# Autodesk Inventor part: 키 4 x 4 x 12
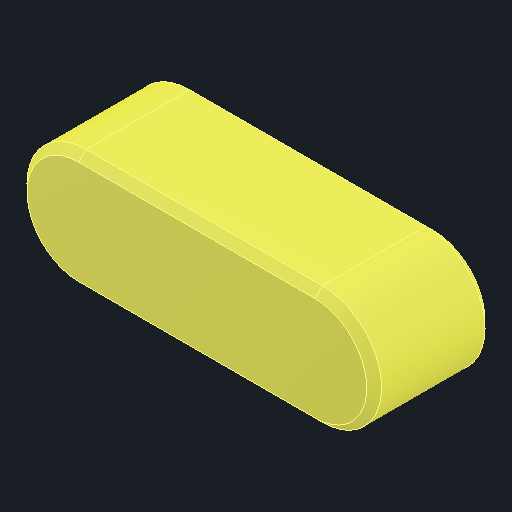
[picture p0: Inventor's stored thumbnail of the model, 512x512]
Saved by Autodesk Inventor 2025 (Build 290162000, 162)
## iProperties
Created: 2025-08
Part Number: 키 4 x 4 x 12
Material: 강철, 연강
Description: 키 및 해당 키홈
Document SubType Name: Modeling
Designer: infra14
Density: 7.85 g/cm^3
Appearance: 기본값
Author: jhkim
Sending System: Autodesk Inventor 2026
Preprocessor: ST-DEVELOPER v20.1
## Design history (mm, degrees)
feature "Solid1"
node "솔리드1"
